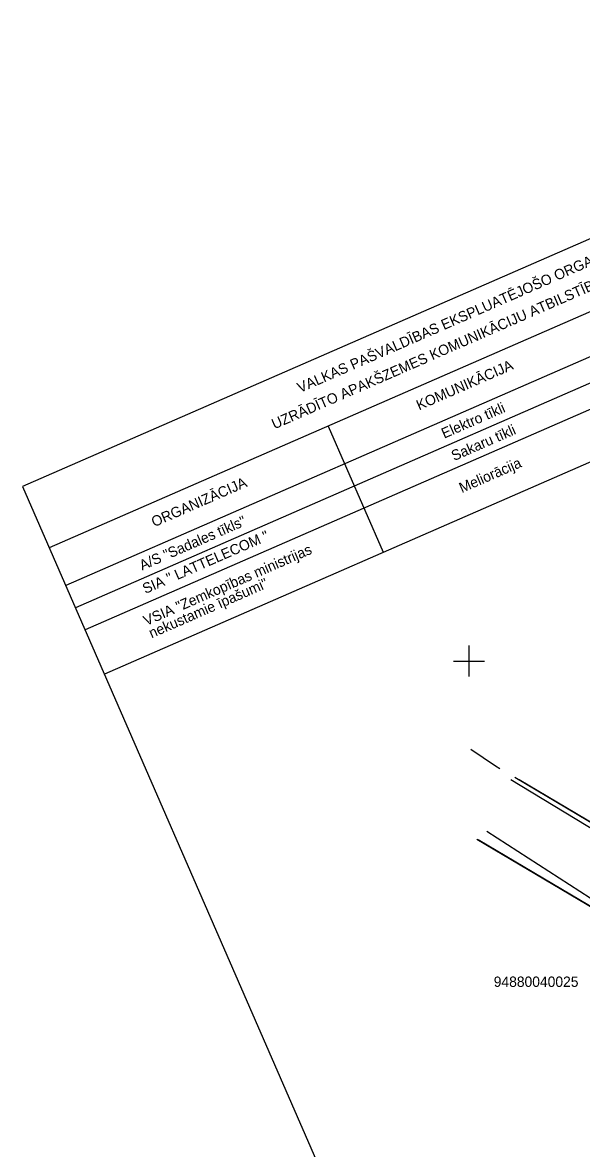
# Model space of a CAD drawing. Extents: x 616607 to 617499, y 408385 to 409695.
# Drawn here: x 616606.9 to 616660.9, y 408453 to 408561.6 of the extents above; entities that cross this region are included whole.
import ezdxf

# ---------------------------------------------------------------- set-up
doc = ezdxf.new("R2010")
doc.units = 0
for name, color, linetype in [('BUVE_INZE_VEKT_####_#', 7, 'Continuous'), ('GEOD_ELEM_####_####_#', 7, 'Continuous'), ('RAMI_PLAN_####_TKST_#', 7, 'Continuous'), ('ROBZ_IERR_####_####_#', 7, 'Continuous'), ('ROBZ_IERR_####_TKST_#', 7, 'Continuous'), ('ROBZ_PROJ_####_####_#', 7, 'Continuous')]:
    doc.layers.add(name, color=color, linetype=linetype)

# ---------------------------------------------------------------- blocks, each defined once
blk = doc.blocks.new('KRUSTS')
at = {"layer": 'GEOD_ELEM_####_####_#'}
for p, q in [((0, 1.5), (0, 0)), ((-1.5, 0), (0, 0)), ((0, 0), (0, -1.5)), ((0, 0), (1.5, 0))]:
    blk.add_line(p, q, dxfattribs=at)

msp = doc.modelspace()

# ---------------------------------------------------------------- linework, layer by layer
at = {"layer": 'BUVE_INZE_VEKT_####_#'}
for points in [[(616654.06, 408488.57), (616669.82, 408479.02), (616700.99, 408461.29)], [(616697.26, 408456.51), (616666.7, 408473.89), (616651.74, 408483.57)]]:
    msp.add_lwpolyline(points, dxfattribs=at)
at = {"layer": 'RAMI_PLAN_####_TKST_#'}
for p, q in [((616996.58, 408686.96), (616606.9, 408516.85)), ((616705.01, 408552.63), (616609.48, 408510.93)), ((616706.6, 408548.98), (616611.07, 408507.29)), ((616707.53, 408546.85), (616612, 408505.15)), ((616708.46, 408544.71), (616612.93, 408503.02)), ((616710.32, 408540.44), (616614.8, 408498.75)), ((616636.41, 408522.68), (616641.73, 408510.5)), ((616606.9, 408516.85), (616664.27, 408385.42))]:
    msp.add_line(p, q, dxfattribs=at)
at = {"layer": 'ROBZ_IERR_####_####_#'}
for points in [[(616717.13, 408556.58), (616730.49, 408522.34), (616708.65, 408488.2), (616688.05, 408471.5), (616671.46, 408478.71), (616654.85, 408488.54)], [(616650.77, 408482.82), (616667.9, 408472.69), (616676.23, 408468.08), (616664.4, 408456.37)]]:
    msp.add_lwpolyline(points, dxfattribs=at)
at = {"layer": 'ROBZ_PROJ_####_####_#'}
for points in [[(616650.19, 408491.5), (616652.58, 408489.88), (616652.99, 408489.64)], [(616654.44, 408488.79), (616671.46, 408478.71), (616688.05, 408471.5), (616695.31, 408466.84), (616704.66, 408460.84)], [(616696.25, 408455.92), (616682.56, 408464.23), (616676.23, 408468.08), (616667.9, 408472.69), (616650.91, 408482.74)]]:
    msp.add_lwpolyline(points, dxfattribs=at)

# ---------------------------------------------------------------- block references
at = {"layer": 'GEOD_ELEM_####_####_#'}
msp.add_blockref('KRUSTS', (616650, 408500), dxfattribs=at)

# ---------------------------------------------------------------- texts
at = {"layer": 'RAMI_PLAN_####_TKST_#'}
for s, p in [('VALKAS PAŠVALDĪBAS EKSPLUATĒJOŠO ORGANIZĀCIJU APLIECINĀJUMS PAR PLĀNĀ', (616633.69, 408525.87)), ('UZRĀDĪTO APAKŠZEMES KOMUNIKĀCIJU ATBILSTĪBU ŠO ORGANIZĀCIJU ARHĪVU MATERIĀLIEM', (616631.22, 408522.36)), ('KOMUNIKĀCIJA', (616645.19, 408524.18)), ('Elektro tīkli', (616647.61, 408521.46)), ('Sakaru tīkli', (616648.57, 408519.3)), ('Meliorācija', (616649.32, 408516.21)), ('ORGANIZĀCIJA', (616619.61, 408512.92)), ('A/S "Sadales tīkls"', (616618.45, 408508.73)), ('SIA " LATTELECOM "', (616618.75, 408506.47)), ('VSIA "Zemkopības ministrijas ', (616618.84, 408503.38)), ('nekustamie īpašumi"', (616619.36, 408502.19))]:
    msp.add_text(s, height=1, rotation=23.5821, dxfattribs=at).set_placement(p)
at = {"layer": 'ROBZ_IERR_####_TKST_#'}
msp.add_text('94880040025', height=1, dxfattribs=at).set_placement((616652.4, 408468.56))

doc.saveas('drawing.dxf')
